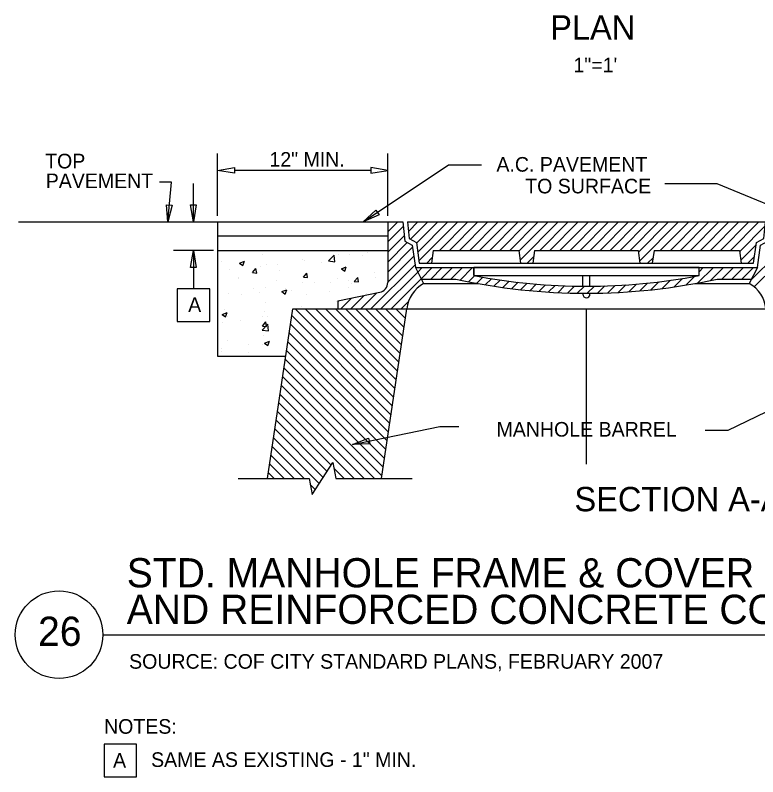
# Model space of a CAD drawing. Extents: x 6712067 to 6713867, y 1867712 to 1869162.
# Drawn here: x 6713311.7 to 6713616.6, y 1868441.2 to 1868753.9 of the extents above; entities that cross this region are included whole.
import ezdxf

# ---------------------------------------------------------------- set-up
doc = ezdxf.new("R2010")
doc.units = 0
for name, color, linetype in [('G-MARK', 7, 'Continuous'), ('G-TEXT', 7, 'Continuous'), ('Misc CnstDet(22)', 7, 'Continuous')]:
    doc.layers.add(name, color=color, linetype=linetype)

msp = doc.modelspace()

# ---------------------------------------------------------------- linework, layer by layer
at = {"layer": 'G-MARK'}
for p, q in [((6713394.7, 1868671.47), (6713394.7, 1868697.18)), ((6713464.66, 1868671.47), (6713464.66, 1868697.18)), ((6713457.66, 1868690.18), (6713401.7, 1868690.18)), ((6713384.87, 1868669.03), (6713384.87, 1868684.86)), ((6713393.06, 1868657.37), (6713376.68, 1868657.37)), ((6713384.87, 1868657.37), (6713384.87, 1868641.51)), ((6713403.18, 1868563.73), (6713432.35, 1868563.73)), ((6713443.37, 1868563.73), (6713474.74, 1868563.73))]:
    msp.add_line(p, q, dxfattribs=at)
for points in [[(6713454.62, 1868669.03), (6713489.69, 1868692.53), (6713503.18, 1868692.53)], [(6713374.36, 1868669.03), (6713375.85, 1868685.35), (6713370.95, 1868685.35)], [(6713637.9, 1868669.03), (6713599.99, 1868684.64), (6713578.45, 1868684.64)], [(6713635.84, 1868598.59), (6713604.3, 1868583.37), (6713595.06, 1868583.37)], [(6713450.16, 1868577.66), (6713486.04, 1868585), (6713493.9, 1868585)], [(6713432.35, 1868563.73), (6713433.59, 1868557.19), (6713442.15, 1868570.27), (6713443.37, 1868563.73)]]:
    msp.add_lwpolyline(points, dxfattribs=at)
msp.add_lwpolyline([(6713378.17, 1868628.11), (6713391.57, 1868628.11), (6713391.57, 1868641.51), (6713378.17, 1868641.51)], close=True, dxfattribs=at)
at = {"layer": 'G-TEXT'}
for points in [[(6713401.7, 1868691.35), (6713401.7, 1868689.01), (6713394.7, 1868690.18)], [(6713457.66, 1868691.35), (6713457.66, 1868689.01), (6713464.66, 1868690.18)], [(6713376.12, 1868675.9), (6713374.36, 1868669.03), (6713373.8, 1868676.09)], [(6713386.04, 1868676.03), (6713384.87, 1868669.03), (6713383.7, 1868676.03)], [(6713461.09, 1868671.94), (6713454.62, 1868669.03), (6713459.78, 1868673.89)], [(6713383.7, 1868650.37), (6713384.87, 1868657.37), (6713386.04, 1868650.37)], [(6713457.26, 1868577.91), (6713450.16, 1868577.66), (6713456.8, 1868580.21)]]:
    msp.add_lwpolyline(points, close=True, dxfattribs=at)
at = {"layer": 'Misc CnstDet(22)'}
for p, q in [((6713394.7, 1868690.18), (6713394.7, 1868690.18)), ((6713313.08, 1868669.03), (6713470.91, 1868669.03)), ((6713394.69, 1868669.03), (6713394.69, 1868613.95)), ((6713394.7, 1868669.04), (6713394.7, 1868669.04)), ((6713464.65, 1868669.03), (6713464.65, 1868644.19)), ((6713464.65, 1868664.92), (6713468.75, 1868669.03)), ((6713464.66, 1868669.04), (6713464.66, 1868669.04)), ((6713472.73, 1868669.03), (6713619.8, 1868669.03)), ((6713472.75, 1868668.91), (6713472.86, 1868669.03)), ((6713473.14, 1868665.17), (6713476.99, 1868669.03)), ((6713474.03, 1868661.94), (6713481.1, 1868669.03)), ((6713476.49, 1868660.28), (6713485.23, 1868669.03)), ((6713476.97, 1868656.66), (6713489.36, 1868669.03)), ((6713477.48, 1868653.03), (6713493.47, 1868669.03)), ((6713485.94, 1868657.37), (6713497.6, 1868669.03)), ((6713490.05, 1868657.37), (6713501.71, 1868669.03)), ((6713494.18, 1868657.37), (6713505.84, 1868669.03)), ((6713498.32, 1868657.37), (6713509.97, 1868669.03)), ((6713502.42, 1868657.37), (6713514.08, 1868669.03)), ((6713506.55, 1868657.37), (6713518.21, 1868669.03)), ((6713510.66, 1868657.37), (6713522.32, 1868669.03)), ((6713514.79, 1868657.37), (6713526.45, 1868669.03)), ((6713518.54, 1868656.98), (6713530.58, 1868669.03)), ((6713519.04, 1868653.38), (6713534.69, 1868669.03)), ((6713527.16, 1868657.37), (6713538.82, 1868669.03)), ((6713531.27, 1868657.37), (6713542.93, 1868669.03)), ((6713535.4, 1868657.37), (6713547.06, 1868669.03)), ((6713539.54, 1868657.37), (6713551.19, 1868669.03)), ((6713543.64, 1868657.37), (6713555.3, 1868669.03)), ((6713547.77, 1868657.37), (6713559.43, 1868669.03)), ((6713551.88, 1868657.37), (6713563.54, 1868669.03)), ((6713556.01, 1868657.37), (6713567.67, 1868669.03)), ((6713560.15, 1868657.37), (6713571.8, 1868669.03)), ((6713564.25, 1868657.37), (6713575.91, 1868669.03)), ((6713567.65, 1868656.63), (6713580.04, 1868669.03)), ((6713568.16, 1868653.01), (6713584.15, 1868669.03)), ((6713576.62, 1868657.37), (6713588.28, 1868669.03)), ((6713580.76, 1868657.37), (6713592.41, 1868669.03)), ((6713584.86, 1868657.37), (6713596.52, 1868669.03)), ((6713588.99, 1868657.37), (6713600.65, 1868669.03)), ((6713593.1, 1868657.37), (6713604.76, 1868669.03)), ((6713597.23, 1868657.37), (6713608.89, 1868669.03)), ((6713601.37, 1868657.37), (6713613.02, 1868669.03)), ((6713605.47, 1868657.37), (6713617.13, 1868669.03)), ((6713464.65, 1868660.81), (6713471.1, 1868667.24)), ((6713609.21, 1868656.96), (6713619.63, 1868667.38)), ((6713464.65, 1868663.2), (6713394.69, 1868663.2)), ((6713464.65, 1868656.68), (6713471.49, 1868663.52)), ((6713464.65, 1868652.57), (6713472.68, 1868660.6)), ((6713609.7, 1868653.35), (6713615.96, 1868659.6)), ((6713613.85, 1868645.11), (6713627.87, 1868659.16)), ((6713394.69, 1868657.37), (6713464.65, 1868657.37)), ((6713456.25, 1868656.45), (6713456.25, 1868656.45)), ((6713464.65, 1868648.44), (6713474.86, 1868658.65)), ((6713483.37, 1868657.37), (6713482.66, 1868652.09)), ((6713483.37, 1868657.37), (6713518.49, 1868657.37)), ((6713518.49, 1868657.37), (6713519.22, 1868652.09)), ((6713524.98, 1868657.37), (6713524.27, 1868652.09)), ((6713524.98, 1868657.37), (6713567.54, 1868657.37)), ((6713567.54, 1868657.37), (6713568.27, 1868652.09)), ((6713574.05, 1868657.37), (6713573.32, 1868652.09)), ((6713574.05, 1868657.37), (6713609.15, 1868657.37)), ((6713609.15, 1868657.37), (6713609.88, 1868652.09)), ((6713403.73, 1868652.16), (6713405.78, 1868652.94)), ((6713405.18, 1868651.17), (6713405.78, 1868652.94)), ((6713413.4, 1868655.67), (6713413.4, 1868655.67)), ((6713429.83, 1868653.74), (6713429.83, 1868653.74)), ((6713430.54, 1868653.05), (6713430.54, 1868653.05)), ((6713440.36, 1868653.05), (6713442.64, 1868655.44)), ((6713440.36, 1868653.05), (6713442.96, 1868652.66)), ((6713442.96, 1868652.66), (6713442.64, 1868655.42)), ((6713444.54, 1868655.6), (6713444.54, 1868655.6)), ((6713448.97, 1868655.49), (6713448.97, 1868655.49)), ((6713454.39, 1868655.1), (6713454.39, 1868655.1)), ((6713464.65, 1868644.31), (6713475.36, 1868655.03)), ((6713480.67, 1868652.09), (6713482.98, 1868654.41)), ((6713521.89, 1868652.09), (6713524.64, 1868654.84)), ((6713571.37, 1868652.09), (6713573.64, 1868654.36)), ((6713612.59, 1868652.09), (6713615.3, 1868654.82)), ((6713615.2, 1868642.34), (6713627.87, 1868655.03)), ((6713396.39, 1868652.76), (6713396.39, 1868652.76)), ((6713403.73, 1868652.16), (6713405.18, 1868651.2)), ((6713409.15, 1868648.21), (6713410.55, 1868649.89)), ((6713410.87, 1868648.05), (6713410.55, 1868649.89)), ((6713412.23, 1868650.64), (6713412.23, 1868650.64)), ((6713414.87, 1868651.68), (6713414.87, 1868651.68)), ((6713419.5, 1868651.61), (6713419.5, 1868651.61)), ((6713437.38, 1868652.18), (6713437.38, 1868652.18)), ((6713445.62, 1868649.84), (6713447.66, 1868650.62)), ((6713445.62, 1868649.84), (6713447.07, 1868648.85)), ((6713447.07, 1868648.85), (6713447.66, 1868650.6)), ((6713457.76, 1868633.32), (6713475.87, 1868651.4)), ((6713476.03, 1868650.28), (6713479.4, 1868643.74)), ((6713476.99, 1868648.42), (6713478.85, 1868650.28)), ((6713478.39, 1868645.69), (6713482.98, 1868650.28)), ((6713482.39, 1868645.55), (6713487.09, 1868650.28)), ((6713486.5, 1868645.55), (6713491.22, 1868650.28)), ((6713490.63, 1868645.55), (6713495.33, 1868650.28)), ((6713494.37, 1868645.18), (6713499.46, 1868650.28)), ((6713499.99, 1868647.02), (6713499.99, 1868650.28)), ((6713592.09, 1868643.97), (6713598.4, 1868650.28)), ((6713592.55, 1868647.02), (6713592.55, 1868650.28)), ((6713592.55, 1868648.56), (6713594.27, 1868650.28)), ((6713597.23, 1868644.98), (6713602.51, 1868650.28)), ((6713601.92, 1868645.55), (6713606.64, 1868650.28)), ((6713606.05, 1868645.55), (6713610.75, 1868650.28)), ((6713610.16, 1868645.55), (6713614.88, 1868650.28)), ((6713616.51, 1868650.28), (6713613.14, 1868643.74)), ((6713399.72, 1868649.5), (6713399.72, 1868649.5)), ((6713409.15, 1868648.21), (6713410.9, 1868648.05)), ((6713420.37, 1868649.27), (6713420.37, 1868649.27)), ((6713430.06, 1868646.38), (6713431.46, 1868648.05)), ((6713431.78, 1868646.24), (6713431.46, 1868648.05)), ((6713459.32, 1868648.07), (6713459.32, 1868648.07)), ((6713461.89, 1868633.32), (6713476.99, 1868648.42)), ((6713497.79, 1868644.47), (6713500.27, 1868646.97)), ((6713499.99, 1868647.02), (6713592.55, 1868647.02)), ((6713544.81, 1868642.63), (6713544.81, 1868647.02)), ((6713547.73, 1868642.63), (6713547.73, 1868647.02)), ((6713587.07, 1868643.07), (6713590.67, 1868646.67)), ((6713403.28, 1868645.62), (6713403.28, 1868645.62)), ((6713403.39, 1868646.35), (6713403.39, 1868646.35)), ((6713418.84, 1868644.95), (6713418.84, 1868644.95)), ((6713429.46, 1868644.03), (6713429.46, 1868644.03)), ((6713430.06, 1868646.38), (6713431.78, 1868646.24)), ((6713434.4, 1868644.31), (6713434.4, 1868644.31)), ((6713441.28, 1868643.99), (6713441.28, 1868643.99)), ((6713444.2, 1868645.89), (6713444.2, 1868645.89)), ((6713448.58, 1868644.95), (6713448.58, 1868644.95)), ((6713449.96, 1868643.64), (6713449.96, 1868643.64)), ((6713450.94, 1868644.56), (6713452.37, 1868646.24)), ((6713450.94, 1868644.56), (6713452.69, 1868644.4)), ((6713452.69, 1868644.4), (6713452.37, 1868646.21)), ((6713459.62, 1868646.4), (6713459.62, 1868646.4)), ((6713466.02, 1868633.32), (6713478.39, 1868645.69)), ((6713478.46, 1868645.55), (6713492.65, 1868645.55)), ((6713479.36, 1868643.74), (6713501.69, 1868643.74)), ((6713501.25, 1868643.83), (6713503.75, 1868646.33)), ((6713504.74, 1868643.21), (6713507.29, 1868645.73)), ((6713508.3, 1868642.63), (6713510.87, 1868645.18)), ((6713511.9, 1868642.11), (6713514.5, 1868644.7)), ((6713515.53, 1868641.62), (6713518.17, 1868644.24)), ((6713519.22, 1868641.19), (6713521.89, 1868643.85)), ((6713568.18, 1868640.68), (6713571.41, 1868643.92)), ((6713572.75, 1868641.12), (6713576.07, 1868644.45)), ((6713577.43, 1868641.67), (6713580.82, 1868645.07)), ((6713582.2, 1868642.31), (6713585.69, 1868645.8)), ((6713590.83, 1868643.74), (6713613.16, 1868643.74)), ((6713599.9, 1868645.55), (6713614.08, 1868645.55)), ((6713409.43, 1868641.69), (6713409.43, 1868641.69)), ((6713414.5, 1868641.97), (6713414.5, 1868641.97)), ((6713421.13, 1868640.43), (6713423.17, 1868641.21)), ((6713421.13, 1868640.43), (6713422.58, 1868639.44)), ((6713422.58, 1868639.44), (6713423.17, 1868641.21)), ((6713422.88, 1868641.56), (6713422.88, 1868641.56)), ((6713424.99, 1868641.05), (6713424.99, 1868641.05)), ((6713440.55, 1868640.39), (6713440.55, 1868640.39)), ((6713448.51, 1868641.99), (6713448.51, 1868641.99)), ((6713522.96, 1868640.8), (6713525.65, 1868643.48)), ((6713526.77, 1868640.48), (6713529.48, 1868643.21)), ((6713530.61, 1868640.2), (6713533.38, 1868642.98)), ((6713534.53, 1868639.99), (6713537.33, 1868642.79)), ((6713538.48, 1868639.83), (6713541.33, 1868642.68)), ((6713542.52, 1868639.74), (6713545.41, 1868642.63)), ((6713546.6, 1868639.72), (6713549.54, 1868642.66)), ((6713550.78, 1868639.77), (6713553.77, 1868642.75)), ((6713555, 1868639.86), (6713558.06, 1868642.91)), ((6713559.32, 1868640.06), (6713562.42, 1868643.16)), ((6713563.7, 1868640.32), (6713566.87, 1868643.48)), ((6713399.37, 1868639.79), (6713399.37, 1868639.79)), ((6713404.54, 1868639.15), (6713404.54, 1868639.15)), ((6713411.84, 1868640.11), (6713411.84, 1868640.11)), ((6713431.51, 1868639.05), (6713431.51, 1868639.05)), ((6713444.24, 1868636.58), (6713461.36, 1868640.13)), ((6713445.41, 1868633.32), (6713449.82, 1868637.75)), ((6713449.52, 1868633.32), (6713455.03, 1868638.82)), ((6713453.65, 1868633.32), (6713460.24, 1868639.9)), ((6713456.11, 1868639.72), (6713456.11, 1868639.72)), ((6713544.81, 1868639.38), (6713544.81, 1868639.72)), ((6713547.73, 1868639.38), (6713547.73, 1868639.72)), ((6713414.52, 1868636.14), (6713414.52, 1868636.14)), ((6713429.12, 1868634.33), (6713429.12, 1868634.33)), ((6713443.83, 1868636.19), (6713443.83, 1868636.19)), ((6713444.24, 1868636.28), (6713444.61, 1868636.64)), ((6713444.24, 1868636.58), (6713444.24, 1868633.32)), ((6713470.13, 1868633.32), (6713473.21, 1868636.39)), ((6713396.64, 1868631.02), (6713398.69, 1868631.8)), ((6713396.64, 1868631.02), (6713398.09, 1868630.06)), ((6713397.51, 1868633.22), (6713397.51, 1868633.22)), ((6713398.09, 1868630.03), (6713398.69, 1868631.8)), ((6713414.15, 1868632.28), (6713414.15, 1868632.28)), ((6713415.23, 1868563.73), (6713425.68, 1868633.32)), ((6713425.68, 1868633.32), (6713666.87, 1868633.32)), ((6713466.55, 1868593.47), (6713426.71, 1868633.32)), ((6713467.08, 1868597.05), (6713430.82, 1868633.32)), ((6713467.63, 1868600.63), (6713434.95, 1868633.32)), ((6713468.16, 1868604.21), (6713439.08, 1868633.32)), ((6713440.91, 1868633.45), (6713440.91, 1868633.45)), ((6713468.71, 1868607.82), (6713443.19, 1868633.32)), ((6713469.24, 1868611.4), (6713447.32, 1868633.32)), ((6713469.76, 1868614.98), (6713451.43, 1868633.32)), ((6713470.32, 1868618.56), (6713455.56, 1868633.32)), ((6713470.84, 1868622.14), (6713459.69, 1868633.32)), ((6713462.08, 1868563.73), (6713472.52, 1868633.32)), ((6713471.39, 1868625.72), (6713463.8, 1868633.32)), ((6713471.92, 1868629.32), (6713467.93, 1868633.32)), ((6713472.47, 1868632.9), (6713472.04, 1868633.32)), ((6713546.26, 1868569.56), (6713546.26, 1868633.32)), ((6713397.49, 1868630.79), (6713397.49, 1868630.79)), ((6713399.01, 1868630.08), (6713399.01, 1868630.08)), ((6713404.17, 1868628.61), (6713404.17, 1868628.61)), ((6713413.05, 1868630.15), (6713413.05, 1868630.15)), ((6713413.19, 1868626.29), (6713414.59, 1868627.97)), ((6713414.93, 1868626.13), (6713414.59, 1868627.97)), ((6713415.21, 1868630.06), (6713415.21, 1868630.06)), ((6713466, 1868589.89), (6713425.26, 1868630.63)), ((6713396.87, 1868627.65), (6713396.87, 1868627.65)), ((6713413.12, 1868624.66), (6713415.39, 1868627.03)), ((6713413.19, 1868626.29), (6713414.93, 1868626.13)), ((6713415.71, 1868624.27), (6713415.39, 1868627.03)), ((6713465.47, 1868586.31), (6713424.73, 1868627.05)), ((6713413.12, 1868624.66), (6713415.71, 1868624.27)), ((6713413.79, 1868622.58), (6713413.79, 1868622.58)), ((6713464.92, 1868582.73), (6713424.18, 1868623.47)), ((6713398.66, 1868620.39), (6713398.66, 1868620.39)), ((6713407.54, 1868618.58), (6713407.54, 1868618.58)), ((6713413.3, 1868618.77), (6713413.3, 1868618.77)), ((6713414.04, 1868619.29), (6713416.08, 1868620.07)), ((6713414.04, 1868619.29), (6713415.49, 1868618.31)), ((6713415.49, 1868618.31), (6713416.08, 1868620.07)), ((6713464.39, 1868579.13), (6713423.66, 1868619.87)), ((6713396.32, 1868615.83), (6713396.32, 1868615.83)), ((6713396.5, 1868617.11), (6713396.5, 1868617.11)), ((6713463.87, 1868575.55), (6713423.1, 1868616.29)), ((6713394.69, 1868613.95), (6713422.76, 1868613.95)), ((6713407.36, 1868615.25), (6713407.36, 1868615.25)), ((6713463.32, 1868571.97), (6713422.58, 1868612.71)), ((6713462.79, 1868568.39), (6713422.05, 1868609.13)), ((6713462.24, 1868564.81), (6713421.5, 1868605.55)), ((6713459.18, 1868563.73), (6713420.97, 1868601.97)), ((6713455.05, 1868563.73), (6713420.42, 1868598.38)), ((6713450.94, 1868563.73), (6713419.89, 1868594.78)), ((6713441.42, 1868569.15), (6713419.34, 1868591.2)), ((6713439.79, 1868566.64), (6713418.81, 1868587.62)), ((6713438.14, 1868564.16), (6713418.26, 1868584.04)), ((6713436.51, 1868561.66), (6713417.73, 1868580.46)), ((6713430.33, 1868563.73), (6713417.21, 1868576.88)), ((6713426.2, 1868563.73), (6713416.66, 1868573.28)), ((6713422.1, 1868563.73), (6713416.13, 1868569.7)), ((6713417.96, 1868563.73), (6713415.58, 1868566.12)), ((6713446.81, 1868563.73), (6713442.59, 1868567.97)), ((6713434.88, 1868559.18), (6713432.84, 1868561.23)), ((6713347.68, 1868499.57), (6713763.18, 1868499.57))]:
    msp.add_line(p, q, dxfattribs=at)
for points in [[(6713470.91, 1868669.03), (6713471.74, 1868661.11), (6713474.74, 1868659.48), (6713476.03, 1868650.28), (6713616.51, 1868650.28), (6713617.78, 1868659.48), (6713620.78, 1868661.11), (6713621.63, 1868669.03)], [(6713472.73, 1868669.03), (6713473.46, 1868662.26), (6713476.44, 1868660.65), (6713477.61, 1868652.09), (6713614.93, 1868652.09), (6713616.1, 1868660.65), (6713619.08, 1868662.26), (6713619.8, 1868669.03)], [(6713499.99, 1868650.28), (6713499.99, 1868647.02), (6713592.55, 1868647.02), (6713592.55, 1868650.28), (6713499.99, 1868650.28)]]:
    msp.add_lwpolyline(points, dxfattribs=at)
msp.add_lwpolyline([(6713348.15, 1868441.25), (6713361.55, 1868441.25), (6713361.55, 1868454.65), (6713348.15, 1868454.65)], close=True, dxfattribs=at)
msp.add_circle((6713329.68, 1868499.57), 18, dxfattribs=at)
for centre, radius, start, end in [((6713546.27, 1868888.78), 246.15, 259.1621, 280.8379), ((6713460.51, 1868644.19), 4.14, 281.7754, 0), ((6713485.95, 1868631.96), 13.49, 119.2146, 174.2422), ((6713546.27, 1868888.78), 249.06, 257.5657, 282.4343), ((6713606.58, 1868631.96), 13.49, 5.7578, 60.7854), ((6713546.27, 1868639.38), 1.46, 180, 0)]:
    msp.add_arc(centre, radius, start, end, dxfattribs=at)

# ---------------------------------------------------------------- texts
for s, height, p in [('PLAN', 10, (6713531.39, 1868743.89)), ('1"=1\'', 6, (6713540.93, 1868730.43)), ('TOP', 6, (6713323.96, 1868691.01)), ('12" MIN.', 6, (6713416.08, 1868691.72)), ('A.C. PAVEMENT', 6, (6713509.31, 1868689.67)), ('PAVEMENT', 6, (6713324.22, 1868682.9)), ('TO SURFACE', 6, (6713521.13, 1868680.75)), ('A', 6, (6713382.71, 1868632.06)), ('MANHOLE BARREL', 6, (6713509.36, 1868580.89)), ('SECTION A-A', 10, (6713541.35, 1868550.24)), ('STD. MANHOLE FRAME & COVER', 12, (6713357.48, 1868519)), ('AND REINFORCED CONCRETE COLLAR', 12, (6713357.48, 1868504)), ('26', 12, (6713321.06, 1868494.98)), ('SOURCE: COF CITY STANDARD PLANS, FEBRUARY 2007', 6, (6713358.45, 1868485.6)), ('NOTES:', 6, (6713348.16, 1868458.91)), ('A', 6, (6713351.87, 1868445)), ('SAME AS EXISTING - 1" MIN.', 6, (6713367.48, 1868445.28))]:
    msp.add_text(s, height=height, dxfattribs=at).set_placement(p)

doc.saveas('drawing.dxf')
